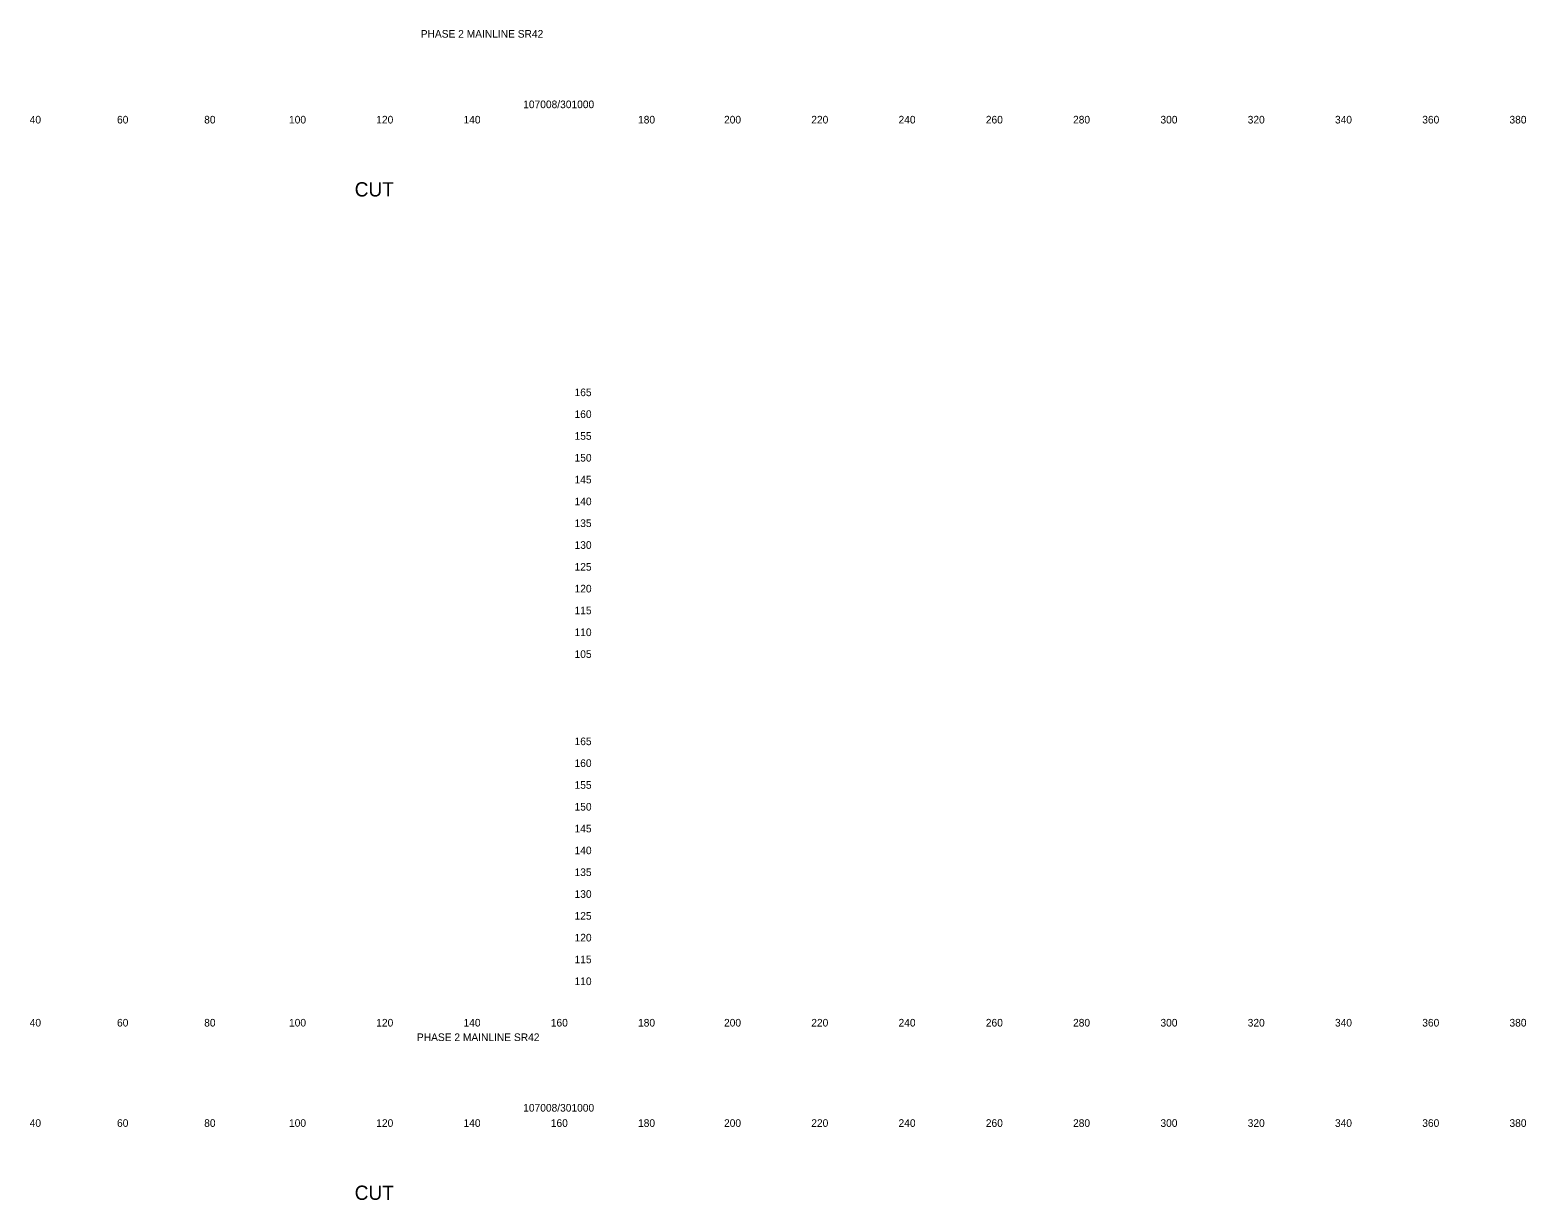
# Model space of a CAD drawing. Extents: x 21281 to 22024, y 6472 to 15208.
# Drawn here: x 21681.3 to 22024.2, y 9195.6 to 9463.8 of the extents above; entities that cross this region are included whole.
import ezdxf

# ---------------------------------------------------------------- set-up
doc = ezdxf.new("R2010")
doc.units = 0
doc.layers.add('XS_SHEET_LABELS_ELEVATION', color=7, linetype='Continuous')
doc.layers.add('XS_SHEET_LABELS_OFFSET', color=7, linetype='Continuous')

msp = doc.modelspace()

# ---------------------------------------------------------------- texts
at = {"layer": 'XS_SHEET_LABELS_ELEVATION'}
for s, p in [('  165  ', (21804.84, 9379.84)), ('  160  ', (21804.84, 9374.84)), ('  155  ', (21804.84, 9369.84)), ('  150  ', (21804.84, 9364.84)), ('  145  ', (21804.84, 9359.84)), ('  140  ', (21804.84, 9354.84)), ('  135  ', (21804.84, 9349.84)), ('  130  ', (21804.84, 9344.84)), ('  125  ', (21804.84, 9339.84)), ('  120  ', (21804.84, 9334.84)), ('  115  ', (21804.84, 9329.84)), ('  110  ', (21804.84, 9324.84)), ('  105  ', (21804.84, 9319.84)), ('  165  ', (21804.84, 9299.84)), ('  160  ', (21804.84, 9294.84)), ('  155  ', (21804.84, 9289.84)), ('  150  ', (21804.84, 9284.84)), ('  145  ', (21804.84, 9279.84)), ('  140  ', (21804.84, 9274.84)), ('  135  ', (21804.84, 9269.84)), ('  130  ', (21804.84, 9264.84)), ('  125  ', (21804.84, 9259.84)), ('  120  ', (21804.84, 9254.84)), ('  115  ', (21804.84, 9249.84)), ('  110  ', (21804.84, 9244.84))]:
    msp.add_text(s, height=1.75, dxfattribs=at).set_placement(p)
at = {"layer": 'XS_SHEET_LABELS_OFFSET'}
for s, height, p in [('PHASE 2 MAINLINE SR42', 1.75, (21770.88, 9462.01)), ('107008/301000', 1.75, (21794.37, 9445.85)), ('  40  ', 1.75, (21679.95, 9442.34)), ('  60  ', 1.75, (21699.97, 9442.34)), ('  80  ', 1.75, (21719.95, 9442.34)), ('  100  ', 1.75, (21739.39, 9442.34)), ('  120  ', 1.75, (21759.39, 9442.34)), ('  140  ', 1.75, (21779.39, 9442.34)), ('  180  ', 1.75, (21819.39, 9442.34)), ('  200  ', 1.75, (21839.1, 9442.34)), ('  220  ', 1.75, (21859.1, 9442.34)), ('  240  ', 1.75, (21879.1, 9442.34)), ('  260  ', 1.75, (21899.11, 9442.34)), ('  280  ', 1.75, (21919.1, 9442.34)), ('  300  ', 1.75, (21939.13, 9442.34)), ('  320  ', 1.75, (21959.13, 9442.34)), ('  340  ', 1.75, (21979.13, 9442.34)), ('  360  ', 1.75, (21999.14, 9442.34)), ('  380  ', 1.75, (22019.13, 9442.34)), ('CUT', 3.273, (21755.74, 9425.61)), ('  40  ', 1.75, (21679.95, 9235.34)), ('  60  ', 1.75, (21699.97, 9235.34)), ('  80  ', 1.75, (21719.95, 9235.34)), ('  100  ', 1.75, (21739.39, 9235.34)), ('  120  ', 1.75, (21759.39, 9235.34)), ('  140  ', 1.75, (21779.39, 9235.34)), ('  160  ', 1.75, (21799.4, 9235.34)), ('  180  ', 1.75, (21819.39, 9235.34)), ('  200  ', 1.75, (21839.1, 9235.34)), ('  220  ', 1.75, (21859.1, 9235.34)), ('  240  ', 1.75, (21879.1, 9235.34)), ('  260  ', 1.75, (21899.11, 9235.34)), ('  280  ', 1.75, (21919.1, 9235.34)), ('  300  ', 1.75, (21939.13, 9235.34)), ('  320  ', 1.75, (21959.13, 9235.34)), ('  340  ', 1.75, (21979.13, 9235.34)), ('  360  ', 1.75, (21999.14, 9235.34)), ('  380  ', 1.75, (22019.13, 9235.34)), ('PHASE 2 MAINLINE SR42', 1.75, (21770.01, 9232.01)), ('107008/301000', 1.75, (21794.37, 9215.84)), ('  40  ', 1.75, (21679.95, 9212.34)), ('  60  ', 1.75, (21699.97, 9212.34)), ('  80  ', 1.75, (21719.95, 9212.34)), ('  100  ', 1.75, (21739.39, 9212.34)), ('  120  ', 1.75, (21759.39, 9212.34)), ('  140  ', 1.75, (21779.39, 9212.34)), ('  160  ', 1.75, (21799.4, 9212.34)), ('  180  ', 1.75, (21819.39, 9212.34)), ('  200  ', 1.75, (21839.1, 9212.34)), ('  220  ', 1.75, (21859.1, 9212.34)), ('  240  ', 1.75, (21879.1, 9212.34)), ('  260  ', 1.75, (21899.11, 9212.34)), ('  280  ', 1.75, (21919.1, 9212.34)), ('  300  ', 1.75, (21939.13, 9212.34)), ('  320  ', 1.75, (21959.13, 9212.34)), ('  340  ', 1.75, (21979.13, 9212.34)), ('  360  ', 1.75, (21999.14, 9212.34)), ('  380  ', 1.75, (22019.13, 9212.34)), ('CUT', 3.273, (21755.74, 9195.61))]:
    msp.add_text(s, height=height, dxfattribs=at).set_placement(p)

doc.saveas('drawing.dxf')
